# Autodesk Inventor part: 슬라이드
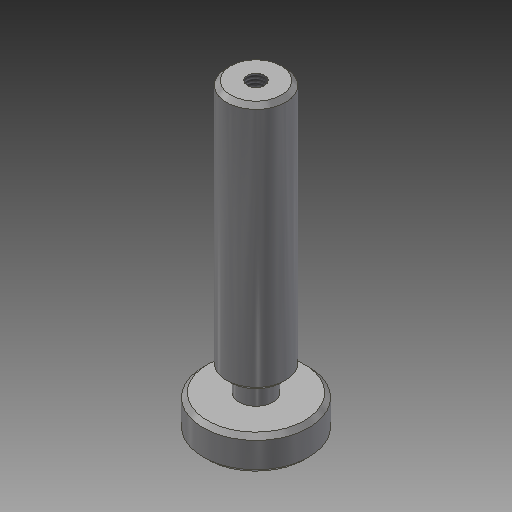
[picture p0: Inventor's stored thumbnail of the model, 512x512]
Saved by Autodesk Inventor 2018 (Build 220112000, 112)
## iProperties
Created: 2015-09
Part Number: 슬라이드
Material: 강철, 연강
Document SubType Name: Modeling
Designer: mduedu
Density: 1 g/cm^3
Appearance: 강철
Author: mduedu
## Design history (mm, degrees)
sketch "스케치1"
  geometry: C1 r 12.5 at (0, 0); 1 further point
  constraints: 1 centre point, 1 coincident
  dimensions: "d0" = 25 diameter of C1
extrude "돌출1" new body sketch "스케치1" distance "d1" = 8; taper "d2" = 0 deg
sketch "스케치2"
  geometry: C1 r 4 at (0, 0); 1 further point
  constraints: 1 centre point, 1 coincident
  dimensions: "d3" = 8 diameter of C1
extrude "돌출2" join sketch "스케치2" distance "d4" = 5; taper "d5" = 0 deg
sketch "스케치3"
  geometry: C1 r 7 at (0, 0); 1 further point
  constraints: 1 centre point, 1 coincident
  dimensions: "d6" = 14 diameter of C1
extrude "돌출3" join sketch "스케치3" distance "d7" = 59; taper "d8" = 0 deg
hole "구멍1" diameter "d11" = 4.134; stored, may be unused: countersink angle "d15" = 90 deg, drill point angle "d17" = 118 deg; dims "d9" = 10, "d10" = 10, "d12" = 9, "d13" = 4, "d14" = 2, "d16" = 12
chamfer "모따기1" distance "d18" = 1; stored, may be unused: second distance "d19" = 2, angle "d20" = 45 deg
node "솔리드1"
